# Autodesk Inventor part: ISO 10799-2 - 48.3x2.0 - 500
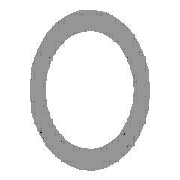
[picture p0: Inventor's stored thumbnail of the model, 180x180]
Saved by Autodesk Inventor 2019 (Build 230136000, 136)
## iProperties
IsCustomPart: 1
Created: 2018-07
Part Number: ISO 10799-2 - 48.3x2.0 - 500
Material: Acier, doux
Description: Aciers de construction - Coupes creuses profilées formées à froid, soudées
Document SubType Name: Modeling
Standard: ISO
Designer: Fabian Perrée
Standard Revision: First edition 2011-09-15
Standards Organization: ISO
Language: fr-FR
Size Designation: 48.3x2.0
Categories: <MemberInstance><Categories><Category DisplayName="Profilés" InternalName="089c4875-fa83-4c05-b084-43b9cc11f5ed" Mnemonic="GRDR"><CategoryParameter DisplayName=
Stock Number: 48.3x2.0
Density: 7.85 g/cm^3
Appearance: Semi-poli
Mass: 1103.72 g
Surface Area: 1414.8 cm^2
Volume: 140.601 cm^3
_CCFamilyMember: 14
_CCFamilyDisplayName: ISO 10799-2 (Profils creux circulaires - Formés à froid) - Aciers de construction - Coupes creuses profilées formées à froid, soudées
_FrameMemberDoc: Frame Member File
_Version: 15.0.0
_GetPNFromCC: 1
G_L: 500,000 mm
G_W: 48,300 mm
G_H: 48,300 mm
+827D7E4F-AC72-4F13-A4D1-31AC1668D8DC+DETAILDECOUPE1: Grugeage
Author: Fabian Perrée
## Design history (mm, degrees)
node "Plan de départ"
node "Plan de fin"
sketch "Esquisse"
  geometry: C1 r 22.15 at (0, 0); C2 r 24.15 at (0, 0); 2 further points
  constraints: 3 coincident, 2 centre point
  dimensions: "d0" = 48.3 diameter of C2 (= G_H); "d1" = 2 radial gap between concentric circles of C2 C1 (= G_T)
extrude "Corps" new body sketch "Esquisse" stored distance "d2" = 500 (= G_L); taper "d3" = 0 deg
node "Driven Length"
  sketch "Sketch3"
    geometry: L1 (0, 0)-(10, 0) reference
    constraints: 2 end point, 1 horizontal
  workplane "Work Plane3"
  sketch "Sketch4"
    geometry: L1 (-2, 0)-(12, 0) reference; L2 (-2, 500)-(12, 500) reference
    dimensions: "d7" = 500 distance between parallel lines of L1 L2 (derived)
body "Solid1"
feature "Sculpter1"
feature "Combiner1"
body "Srf14"
body "Srf15"
node "Solide6"
feature "Surface1"
body "Srf13"
feature "Carreau délimité9" dims "d24" = 5, "d25" = 0
feature "Carreau délimité10" dims "d26" = 5, "d27" = 0
other parameters: "G_H" = 48.3 [user parameter; used in 1 equation term], "G_T" = 2 [user parameter; used in 1 equation term], "G_L" = 500 (= d7) [user parameter; used in 1 equation term], "G_OFFSET_START" = 0 [user parameter; used in 1 equation term], "G_OFFSET_END" = 0 [user parameter; used in 1 equation term], "d4" = 0 (computed from G_OFFSET_START), "d5" = 500 (= G_OFFSET_END + B_L), "B_L" = 500 [user parameter; used in 1 equation term], "d6" = 90 deg, "MAS" = 0.228 [user parameter]
